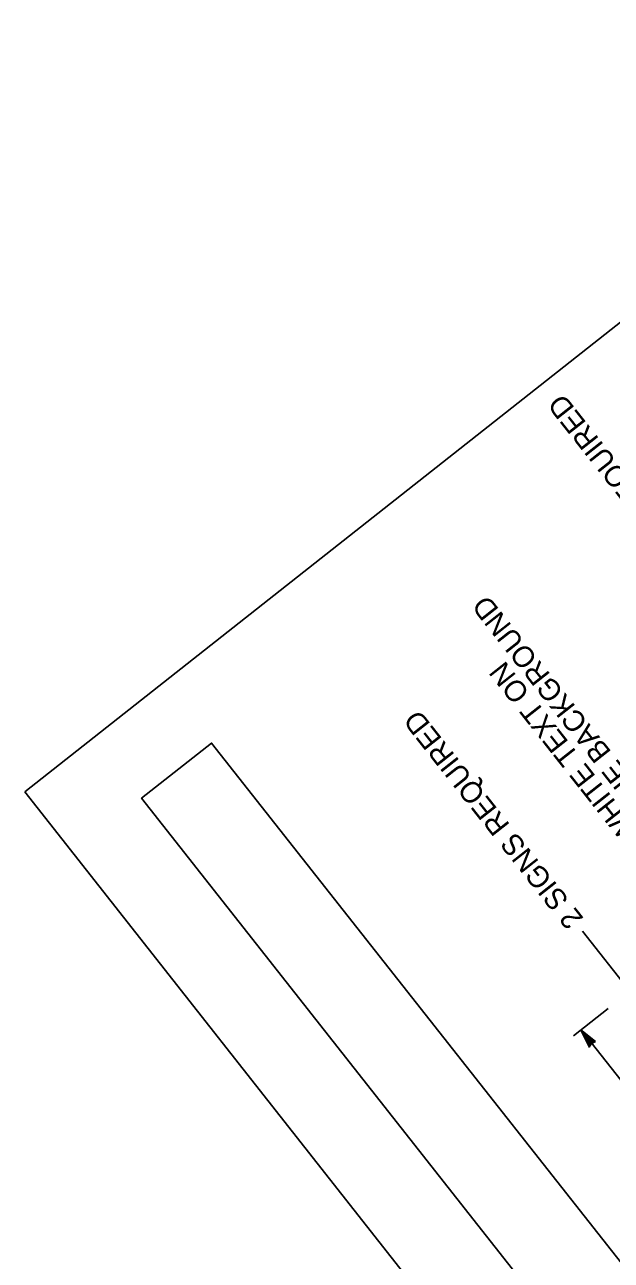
# Model space of a CAD drawing. Extents: x 671946 to 673995, y 1673066 to 1674936.
# Drawn here: x 672311.5 to 672428.5, y 1673764.1 to 1674010.5 of the extents above; entities that cross this region are included whole.
import ezdxf

# ---------------------------------------------------------------- set-up
doc = ezdxf.new("R2010")
doc.units = 0
doc.layers.add('C-ANNO-SYMB', color=7, linetype='Continuous')
doc.layers.add('Level 1', color=7, linetype='Continuous')

msp = doc.modelspace()

# ---------------------------------------------------------------- linework, layer by layer
at = {"layer": 'C-ANNO-SYMB'}
msp.add_lwpolyline([(672469.46, 1673714.17), (672348.81, 1673867.22), (672334.83, 1673856.2), (672455.48, 1673703.15)], close=True, dxfattribs=at)
at = {"layer": 'Level 1'}
for p, q in [((672311.51, 1673857.49), (672505.58, 1674010.48)), ((672451.3, 1673680.17), (672311.51, 1673857.49)), ((672432.44, 1673817.46), (672422.78, 1673829.71)), ((672427.93, 1673814.3), (672421.02, 1673808.85)), ((672424.17, 1673806.53), (672422.47, 1673809.99)), ((672422.47, 1673809.99), (672425.38, 1673807.67)), ((672430.48, 1673799.9), (672422.5, 1673810.02)), ((672422.83, 1673809.57), (672422.7, 1673809.77)), ((672422.7, 1673809.77), (672425.23, 1673807.69)), ((672424.16, 1673806.89), (672422.73, 1673809.73)), ((672422.73, 1673809.73), (672422.76, 1673809.52)), ((672422.76, 1673809.52), (672423.19, 1673808.73)), ((672424.12, 1673806.72), (672422.83, 1673809.57)), ((672423.19, 1673808.73), (672422.98, 1673809.42)), ((672422.98, 1673809.42), (672425.06, 1673807.69)), ((672424.23, 1673807.01), (672423.08, 1673809.2)), ((672423.08, 1673809.2), (672424.79, 1673807.65)), ((672424.23, 1673807.01), (672423.2, 1673809.13)), ((672423.2, 1673809.13), (672424.93, 1673807.69)), ((672423.8, 1673808.41), (672423.46, 1673808.77)), ((672423.46, 1673808.77), (672423.66, 1673808.33)), ((672424.29, 1673807.19), (672423.54, 1673808.7)), ((672423.54, 1673808.7), (672424.65, 1673807.7)), ((672423.9, 1673808.15), (672423.8, 1673808.41)), ((672424.33, 1673807.35), (672423.81, 1673808.31)), ((672423.81, 1673808.31), (672424.52, 1673807.74)), ((672424.66, 1673807.65), (672423.9, 1673808.15)), ((672424.38, 1673807.46), (672424.11, 1673807.98)), ((672424.11, 1673807.98), (672424.45, 1673807.71)), ((672424.31, 1673807.04), (672424.12, 1673806.72)), ((672424.25, 1673806.9), (672424.16, 1673806.89)), ((672424.66, 1673807.35), (672424.19, 1673806.68)), ((672424.93, 1673807.69), (672424.23, 1673807.01)), ((672424.8, 1673807.55), (672424.23, 1673807.01)), ((672424.79, 1673807.65), (672424.29, 1673807.19)), ((672424.62, 1673807.28), (672424.31, 1673807.04)), ((672424.65, 1673807.7), (672424.33, 1673807.35)), ((672424.52, 1673807.74), (672424.38, 1673807.46)), ((672424.45, 1673807.71), (672424.38, 1673807.63)), ((672424.38, 1673807.63), (672424.39, 1673807.27)), ((672424.39, 1673807.27), (672424.66, 1673807.65)), ((672425.38, 1673807.67), (672424.62, 1673807.28)), ((672425.23, 1673807.69), (672424.66, 1673807.35)), ((672425.06, 1673807.69), (672424.8, 1673807.55))]:
    msp.add_line(p, q, dxfattribs=at)

# ---------------------------------------------------------------- texts
for s, p in [('1 SIGN REQUIRED', (672449.59, 1673898.22)), ('BLUE BACKGROUND', (672438.74, 1673852.66)), ('WHITE TEXT ON', (672434.45, 1673849.28)), ('2 SIGNS REQUIRED', (672423.14, 1673832.25))]:
    msp.add_text(s, height=4.2, rotation=128.2505, dxfattribs=at).set_placement(p)

doc.saveas('drawing.dxf')
